// Mitsubishi GX Works2 project: code_plc_misu_chaytuantu   PLC: FX1S

PROGRAM MAIN
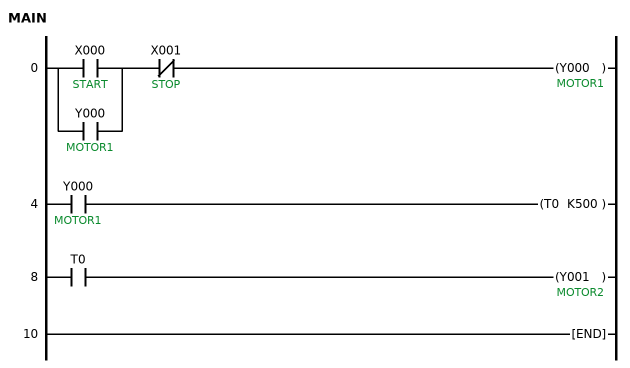
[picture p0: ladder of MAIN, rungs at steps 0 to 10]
0     LD      X000  ; START
      OR      Y000  ; MOTOR1
      ANI     X001  ; STOP
      OUT     Y000  ; MOTOR1
4     LD      Y000  ; MOTOR1
      OUT     T0 K500
8     LD      T0
      OUT     Y001  ; MOTOR2
10    END
END_PROGRAM
